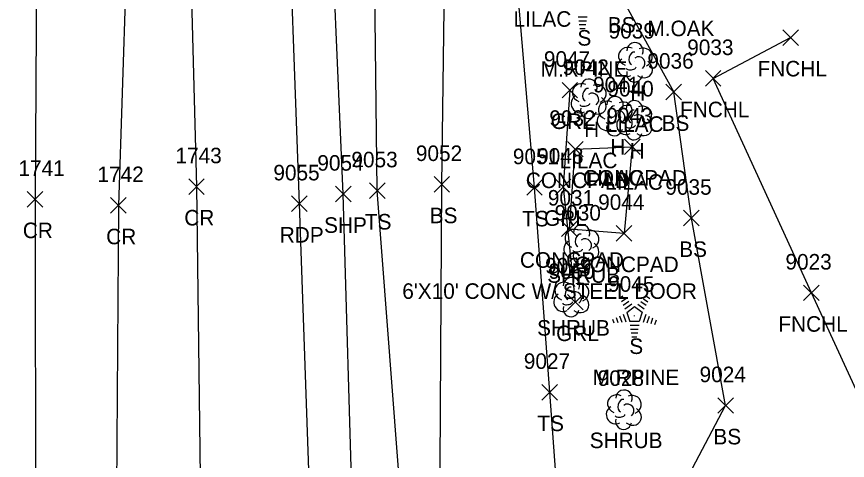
# Model space of a CAD drawing. Extents: x 1462089 to 1464015, y 730534 to 736144.
# Drawn here: x 1463213.7 to 1463320.5, y 735058.9 to 735115.9 of the extents above; entities that cross this region are included whole.
import ezdxf

# ---------------------------------------------------------------- set-up
doc = ezdxf.new("R2010")
doc.units = 0
for name, color, linetype in [('L_A', 7, 'Continuous'), ('L_C', 7, 'Continuous'), ('L_I', 7, 'Continuous'), ('L_TIC', 7, 'Continuous'), ('LELB', 7, 'Continuous'), ('LFNC', 7, 'Continuous'), ('LS', 7, 'Continuous'), ('LSH', 7, 'Continuous'), ('LTC', 7, 'Continuous'), ('LTD', 7, 'Continuous'), ('P_A', 7, 'Continuous'), ('P_I', 7, 'Continuous'), ('P_TIC', 7, 'Continuous'), ('PET', 7, 'Continuous'), ('PRC', 7, 'Continuous'), ('PSP', 7, 'Continuous'), ('R_A', 7, 'Continuous'), ('R_I', 7, 'Continuous'), ('R_TIC', 7, 'Continuous'), ('RGR', 7, 'Continuous')]:
    doc.layers.add(name, color=color, linetype=linetype)

msp = doc.modelspace()

# ---------------------------------------------------------------- linework, layer by layer
at = {"layer": 'L_TIC'}
for points in [[(1463312.17, 735112.24), (1463314.17, 735114.24)], [(1463314.17, 735112.24), (1463312.17, 735114.24)], [(1463302.21, 735106.99), (1463304.21, 735108.99)], [(1463304.21, 735106.99), (1463302.21, 735108.99)], [(1463297.15, 735105.24), (1463299.15, 735107.24)], [(1463299.15, 735105.24), (1463297.15, 735107.24)], [(1463291.82, 735098.19), (1463293.82, 735100.19)], [(1463293.82, 735098.19), (1463291.82, 735100.19)], [(1463284.48, 735097.88), (1463286.48, 735099.88)], [(1463286.48, 735097.88), (1463284.48, 735099.88)], [(1463267.33, 735093.36), (1463269.33, 735095.36)], [(1463269.33, 735093.36), (1463267.33, 735095.36)], [(1463279.24, 735092.95), (1463281.24, 735094.95)], [(1463281.24, 735092.95), (1463279.24, 735094.95)], [(1463259.03, 735092.55), (1463261.03, 735094.55)], [(1463261.03, 735092.55), (1463259.03, 735094.55)], [(1463299.41, 735089.02), (1463301.41, 735091.02)], [(1463301.41, 735089.02), (1463299.41, 735091.02)], [(1463283.73, 735087.63), (1463285.73, 735089.63)], [(1463285.73, 735087.63), (1463283.73, 735089.63)], [(1463283.73, 735087.63), (1463285.73, 735089.63)], [(1463285.73, 735087.63), (1463283.73, 735089.63)], [(1463290.76, 735087.07), (1463292.76, 735089.07)], [(1463292.76, 735087.07), (1463290.76, 735089.07)], [(1463290.76, 735087.07), (1463292.76, 735089.07)], [(1463292.76, 735087.07), (1463290.76, 735089.07)], [(1463314.85, 735079.4), (1463316.85, 735081.4)], [(1463316.85, 735079.4), (1463314.85, 735081.4)], [(1463281.2, 735066.62), (1463283.2, 735068.62)], [(1463283.2, 735066.62), (1463281.2, 735068.62)], [(1463303.81, 735064.91), (1463305.81, 735066.91)], [(1463305.81, 735064.91), (1463303.81, 735066.91)]]:
    msp.add_lwpolyline(points, dxfattribs=at)
at = {"layer": 'LELB'}
for points in [[(1463371.85, 735002), (1463364.09, 734996.08), (1463343.48, 734999.3), (1463307.3, 734996.8), (1463279.82, 735000.59), (1463268.69, 735006.74), (1463262.79, 735015.32), (1463262.16, 735022.4), (1463263.25, 735051.01), (1463260.03, 735093.55), (1463259.51, 735137.92), (1463259.23, 735169.59), (1463258.59, 735220.95), (1463257.15, 735252.7), (1463257.92, 735283.05), (1463254.46, 735323.86), (1463254.58, 735356.52), (1463254.88, 735405.06), (1463258.27, 735455.49), (1463269.4, 735506.21)], [(1463373.96, 735016.62), (1463366.71, 735008.18), (1463344.22, 735006.01), (1463305.54, 735005.28), (1463291, 735003.77), (1463271.88, 735009.52), (1463268.36, 735020.58), (1463268.05, 735051.01), (1463268.33, 735094.36), (1463268.89, 735136.34), (1463266.5, 735167.09), (1463269.8, 735218.26), (1463262.87, 735252.88), (1463272.97, 735283.56), (1463272.77, 735320.3), (1463274.69, 735357.28), (1463267.13, 735402.93), (1463272.15, 735446.53), (1463267.79, 735454.17), (1463268.05, 735456.58), (1463268.56, 735463.07), (1463267.38, 735485.54), (1463275.1, 735504.27)], [(1463291, 735003.77), (1463283.69, 735047.68), (1463282.2, 735067.62), (1463280.24, 735093.95), (1463276.56, 735137.36), (1463277.6, 735165.76), (1463292.4, 735188.02), (1463291.22, 735212.4), (1463294.67, 735266.26), (1463301.55, 735286.5), (1463304.84, 735327.55)], [(1463305.54, 735005.28), (1463294.16, 735045.7), (1463304.81, 735065.91), (1463300.41, 735090.02), (1463298.15, 735106.24), (1463291.23, 735118.87), (1463284.79, 735144.23), (1463285.45, 735166.93), (1463305.02, 735176.52), (1463314.15, 735197.89)]]:
    msp.add_lwpolyline(points, dxfattribs=at)
at = {"layer": 'LFNC'}
msp.add_lwpolyline([(1463373.96, 735016.62), (1463344.8, 735017.08), (1463329.62, 735050.54), (1463315.85, 735080.4), (1463303.21, 735107.99), (1463313.17, 735113.24)], dxfattribs=at)
at = {"layer": 'LS'}
for points in [[(1463284.73, 735088.63), (1463285.48, 735098.88), (1463292.82, 735099.19), (1463291.76, 735088.07)], [(1463284.73, 735088.63), (1463291.76, 735088.07)]]:
    msp.add_lwpolyline(points, dxfattribs=at)
at = {"layer": 'LSH'}
for p, q in [((1463286.25, 735086.7), (1463286.25, 735086.7)), ((1463286.25, 735086.7), (1463286.25, 735086.7)), ((1463284.95, 735079.9), (1463284.95, 735079.9)), ((1463284.95, 735079.9), (1463284.95, 735079.9)), ((1463291.71, 735065.43), (1463291.71, 735065.43)), ((1463291.71, 735065.43), (1463291.71, 735065.43))]:
    msp.add_line(p, q, dxfattribs=at)
for centre in [(1463286.3, 735088.13), (1463285, 735081.33), (1463291.76, 735066.86)]:
    msp.add_arc(centre, 1.05, 335.5272, 180.9563, dxfattribs=at)
for centre, major_axis, ratio, start_param, end_param in [((1463285.46, 735087.37), (1.21, -0.51), 0.895232, 1.570796, 4.712389), ((1463287.29, 735087.28), (-1.14, -0.48), 0.949671, 1.570796, 4.712389), ((1463286.04, 735087.16), (-0.208, -0.792), 0.645439, 3.141593, 6.283185), ((1463286.75, 735086.53), (-0.5, 0.667), 0.989748, 3.141593, 6.283185), ((1463285.17, 735085.99), (0.58, -1.04), 0.959034, 3.141593, 6.283185), ((1463287.25, 735085.87), (-1.09, 0.79), 0.841452, 1.570796, 4.712389), ((1463286.25, 735085.2), (0.26, 1.06), 0.942809, 1.570796, 4.712389), ((1463285.79, 735085.95), (-0.625, -0.083), 0.423636, 0, 3.141593), ((1463284.16, 735080.57), (1.21, -0.51), 0.895232, 1.570796, 4.712389), ((1463284.75, 735080.36), (-0.208, -0.792), 0.645439, 3.141593, 6.283185), ((1463286, 735080.48), (-1.14, -0.48), 0.949671, 1.570796, 4.712389), ((1463283.87, 735079.19), (0.58, -1.04), 0.959034, 3.141593, 6.283185), ((1463285.45, 735079.73), (-0.5, 0.667), 0.989748, 3.141593, 6.283185), ((1463285.95, 735079.07), (-1.09, 0.79), 0.841452, 1.570796, 4.712389), ((1463284.5, 735079.15), (-0.625, -0.083), 0.423636, 0, 3.141593), ((1463284.95, 735078.4), (0.26, 1.06), 0.942809, 1.570796, 4.712389), ((1463290.92, 735066.09), (1.21, -0.51), 0.895232, 1.570796, 4.712389), ((1463292.75, 735066.01), (-1.14, -0.48), 0.949671, 1.570796, 4.712389), ((1463291.5, 735065.89), (-0.208, -0.792), 0.645439, 3.141593, 6.283185), ((1463292.21, 735065.26), (-0.5, 0.667), 0.989748, 3.141593, 6.283185), ((1463290.63, 735064.72), (0.58, -1.04), 0.959034, 3.141593, 6.283185), ((1463292.71, 735064.59), (-1.09, 0.79), 0.841452, 1.570796, 4.712389), ((1463291.71, 735063.93), (0.26, 1.06), 0.942809, 1.570796, 4.712389), ((1463291.25, 735064.68), (-0.625, -0.083), 0.423636, 0, 3.141593)]:
    msp.add_ellipse(centre, major_axis=major_axis, ratio=ratio, start_param=start_param, end_param=end_param, dxfattribs=at)
at = {"layer": 'LTC'}
for p, q in [((1463287, 735115.87), (1463285.86, 735115.87)), ((1463286.92, 735115.37), (1463285.93, 735115.37)), ((1463286.84, 735114.87), (1463286, 735114.87)), ((1463286.75, 735114.37), (1463286.08, 735114.37)), ((1463291.24, 735079.75), (1463291.6, 735080)), ((1463294.64, 735079.99), (1463295.06, 735079.68)), ((1463291.45, 735079.28), (1463291.98, 735079.67)), ((1463291.66, 735078.82), (1463292.37, 735079.33)), ((1463291.87, 735078.35), (1463292.75, 735078.99)), ((1463293.53, 735078.94), (1463294.34, 735078.35)), ((1463293.9, 735079.29), (1463294.58, 735078.8)), ((1463294.27, 735079.64), (1463294.82, 735079.24)), ((1463291.64, 735077.68), (1463291.97, 735076.66)), ((1463292.1, 735077.89), (1463293.11, 735078.63)), ((1463292.1, 735077.89), (1463292.48, 735076.7)), ((1463293.11, 735078.63), (1463294.1, 735077.9)), ((1463294.1, 735077.9), (1463293.71, 735076.7)), ((1463290.28, 735077.03), (1463290.43, 735076.56)), ((1463290.73, 735077.24), (1463290.94, 735076.59)), ((1463291.19, 735077.46), (1463291.46, 735076.62)), ((1463293.71, 735076.7), (1463292.48, 735076.7)), ((1463294.54, 735077.63), (1463294.2, 735076.59)), ((1463294.99, 735077.38), (1463294.7, 735076.5)), ((1463295.43, 735077.13), (1463295.19, 735076.4)), ((1463295.88, 735076.88), (1463295.69, 735076.31)), ((1463293.68, 735076.2), (1463292.53, 735076.2)), ((1463293.59, 735075.7), (1463292.6, 735075.7)), ((1463293.51, 735075.2), (1463292.68, 735075.2)), ((1463293.42, 735074.7), (1463292.75, 735074.7))]:
    msp.add_line(p, q, dxfattribs=at)
at = {"layer": 'LTD'}
for p, q in [((1463293.13, 735110.11), (1463293.13, 735110.11)), ((1463293.13, 735110.11), (1463293.13, 735110.11)), ((1463287.19, 735105.43), (1463287.19, 735105.43)), ((1463287.19, 735105.43), (1463287.19, 735105.43)), ((1463290.54, 735103.19), (1463290.54, 735103.19)), ((1463290.54, 735103.19), (1463290.54, 735103.19)), ((1463293.05, 735102.66), (1463293.05, 735102.66)), ((1463293.05, 735102.66), (1463293.05, 735102.66))]:
    msp.add_line(p, q, dxfattribs=at)
for centre in [(1463293.17, 735111.55), (1463287.24, 735106.86), (1463290.59, 735104.62), (1463293.09, 735104.09)]:
    msp.add_arc(centre, 1.05, 335.5272, 180.9563, dxfattribs=at)
for centre, major_axis, ratio, start_param, end_param in [((1463292.34, 735110.78), (1.21, -0.51), 0.895232, 1.570796, 4.712389), ((1463294.17, 735110.69), (-1.14, -0.48), 0.949671, 1.570796, 4.712389), ((1463292.92, 735110.57), (-0.208, -0.792), 0.645439, 3.141593, 6.283185), ((1463293.63, 735109.94), (-0.5, 0.667), 0.989748, 3.141593, 6.283185), ((1463292.04, 735109.4), (0.58, -1.04), 0.959034, 3.141593, 6.283185), ((1463294.13, 735109.28), (-1.09, 0.79), 0.841452, 1.570796, 4.712389), ((1463293.13, 735108.61), (0.26, 1.06), 0.942809, 1.570796, 4.712389), ((1463292.67, 735109.36), (-0.625, -0.083), 0.423636, 0, 3.141593), ((1463286.4, 735106.1), (1.21, -0.51), 0.895232, 1.570796, 4.712389), ((1463286.98, 735105.89), (-0.208, -0.792), 0.645439, 3.141593, 6.283185), ((1463288.23, 735106.01), (-1.14, -0.48), 0.949671, 1.570796, 4.712389), ((1463286.11, 735104.72), (0.58, -1.04), 0.959034, 3.141593, 6.283185), ((1463287.69, 735105.26), (-0.5, 0.667), 0.989748, 3.141593, 6.283185), ((1463288.19, 735104.6), (-1.09, 0.79), 0.841452, 1.570796, 4.712389), ((1463286.73, 735104.68), (-0.625, -0.083), 0.423636, 0, 3.141593), ((1463289.75, 735103.86), (1.21, -0.51), 0.895232, 1.570796, 4.712389), ((1463290.34, 735103.65), (-0.208, -0.792), 0.645439, 3.141593, 6.283185), ((1463292.26, 735103.32), (1.21, -0.51), 0.895232, 1.570796, 4.712389), ((1463291.59, 735103.77), (-1.14, -0.48), 0.949671, 1.570796, 4.712389), ((1463294.09, 735103.24), (-1.14, -0.48), 0.949671, 1.570796, 4.712389), ((1463287.19, 735103.93), (0.26, 1.06), 0.942809, 1.570796, 4.712389), ((1463289.46, 735102.48), (0.58, -1.04), 0.959034, 3.141593, 6.283185), ((1463291.04, 735103.02), (-0.5, 0.667), 0.989748, 3.141593, 6.283185), ((1463292.84, 735103.12), (-0.208, -0.792), 0.645439, 3.141593, 6.283185), ((1463293.55, 735102.49), (-0.5, 0.667), 0.989748, 3.141593, 6.283185), ((1463290.09, 735102.44), (-0.625, -0.083), 0.423636, 0, 3.141593), ((1463291.96, 735101.95), (0.58, -1.04), 0.959034, 3.141593, 6.283185), ((1463291.54, 735102.36), (-1.09, 0.79), 0.841452, 1.570796, 4.712389), ((1463294.05, 735101.83), (-1.09, 0.79), 0.841452, 1.570796, 4.712389), ((1463290.54, 735101.69), (0.26, 1.06), 0.942809, 1.570796, 4.712389), ((1463293.05, 735101.16), (0.26, 1.06), 0.942809, 1.570796, 4.712389), ((1463292.59, 735101.91), (-0.625, -0.083), 0.423636, 0, 3.141593)]:
    msp.add_ellipse(centre, major_axis=major_axis, ratio=ratio, start_param=start_param, end_param=end_param, dxfattribs=at)
at = {"layer": 'P_TIC'}
for points in [[(1463235.78, 735093.07), (1463237.78, 735095.07)], [(1463237.78, 735093.07), (1463235.78, 735095.07)], [(1463254.66, 735092.12), (1463256.66, 735094.12)], [(1463256.66, 735092.12), (1463254.66, 735094.12)], [(1463215.02, 735091.44), (1463217.02, 735093.44)], [(1463217.02, 735091.44), (1463215.02, 735093.44)], [(1463225.74, 735090.65), (1463227.74, 735092.65)], [(1463227.74, 735090.65), (1463225.74, 735092.65)], [(1463249.01, 735090.87), (1463251.01, 735092.87)], [(1463251.01, 735090.87), (1463249.01, 735092.87)]]:
    msp.add_lwpolyline(points, dxfattribs=at)
at = {"layer": 'PET'}
msp.add_lwpolyline([(1463255.03, 734720.12), (1463254.12, 734771.84), (1463253.55, 734825), (1463253.11, 734864.1), (1463252.5, 734904.18), (1463252.01, 734932.91), (1463252.21, 734977.68), (1463251.97, 735017.67), (1463251.42, 735051.49), (1463250.01, 735091.87), (1463248.35, 735137.79), (1463247.11, 735168.04), (1463244.5, 735220.45), (1463242.66, 735256.85), (1463241.98, 735280.77), (1463241.22, 735323.55), (1463241.58, 735355.89), (1463243.82, 735405.25), (1463248.55, 735456.35), (1463255.13, 735496.28)], dxfattribs=at)
at = {"layer": 'PRC'}
for points in [[(1463243.54, 735500.8), (1463236.92, 735460.01), (1463232.14, 735413.46), (1463229.79, 735375.51), (1463228.93, 735324.03), (1463227.87, 735282.52), (1463228.15, 735235.1), (1463227.86, 735197.88), (1463228.62, 735149.63), (1463226.74, 735091.65), (1463226.45, 735049), (1463226.35, 735007.34), (1463227.1, 734963.18), (1463227.71, 734927.41), (1463228.78, 734878.14), (1463228.9, 734842.02), (1463228.58, 734798.08), (1463230.75, 734747.1)], [(1463216.67, 735366.03), (1463218.87, 735371.39), (1463218.13, 735319.85), (1463217.07, 735284.13), (1463217.19, 735234.76), (1463216.07, 735198.92), (1463216.37, 735151.27), (1463216.02, 735092.44), (1463216.08, 735049.13), (1463213.65, 735007.29), (1463214.1, 734963.88), (1463214.18, 734928.27), (1463216.39, 734879.15), (1463217.01, 734842.19), (1463217.11, 734797.78), (1463218.92, 734749.04)], [(1463228.93, 735324.03), (1463229.27, 735282.53), (1463230.92, 735235.37), (1463232.41, 735197.7), (1463235.31, 735148.71), (1463236.78, 735094.07), (1463237.32, 735049.95), (1463238.75, 735006.91), (1463239.78, 734964.48), (1463240.55, 734927.63), (1463240.74, 734877.14), (1463241.22, 734842.28), (1463241.52, 734797.52), (1463242.3, 734746.35)]]:
    msp.add_lwpolyline(points, dxfattribs=at)
at = {"layer": 'PSP'}
msp.add_lwpolyline([(1463260.61, 734721.09), (1463259.81, 734771.37), (1463258.83, 734825.03), (1463258.44, 734864.28), (1463257.81, 734904.18), (1463257.86, 734929.75), (1463257.64, 734971.1), (1463257.12, 734983.28), (1463257.63, 735017.78), (1463256.87, 735050.62), (1463255.66, 735093.12), (1463253.72, 735137.76), (1463252.7, 735169.76), (1463249.36, 735221.18), (1463247.14, 735255.65), (1463245.42, 735280.67), (1463244.78, 735323.8), (1463245.26, 735355.71), (1463246.85, 735405.2), (1463251.22, 735455.98), (1463269.22, 735540.32), (1463284.02, 735584.42), (1463301.55, 735626.26)], dxfattribs=at)
at = {"layer": 'R_TIC'}
for points in [[(1463283.79, 735105.48), (1463285.79, 735107.48)], [(1463285.79, 735105.48), (1463283.79, 735107.48)], [(1463282.93, 735093.02), (1463284.93, 735095.02)], [(1463284.93, 735093.02), (1463282.93, 735095.02)], [(1463284.48, 735078.2), (1463286.48, 735080.2)], [(1463286.48, 735078.2), (1463284.48, 735080.2)]]:
    msp.add_lwpolyline(points, dxfattribs=at)
at = {"layer": 'RGR'}
msp.add_lwpolyline([(1463284.79, 735106.48), (1463283.93, 735094.02), (1463285.48, 735079.2)], dxfattribs=at)

# ---------------------------------------------------------------- texts
at = {"layer": 'L_A'}
for s, p in [('BS', (1463289.67, 735113.87)), ('S', (1463285.76, 735112.2)), ('FNCHL', (1463308.92, 735108.24)), ('H', (1463292.56, 735105.11)), ('FNCHL', (1463298.96, 735102.99)), ('H', (1463286.63, 735100.43)), ('BS', (1463296.59, 735101.24)), ('H', (1463289.98, 735098.19)), ('H', (1463292.48, 735097.66)), ('CONCPAD', (1463279.13, 735093.88)), ('CONCPAD', (1463286.47, 735094.19)), ('TS', (1463258.44, 735088.55)), ('BS', (1463266.77, 735089.36)), ('TS', (1463278.65, 735088.95)), ('BS', (1463298.85, 735085.02)), ('CONCPAD', (1463278.37, 735083.63)), ('CONCPAD', (1463278.37, 735083.63)), ('CONCPAD', (1463285.41, 735083.07)), ('CONCPAD', (1463285.41, 735083.07)), ('SHRUB', (1463281.88, 735081.7)), ('SHRUB', (1463280.58, 735074.9)), ('FNCHL', (1463311.6, 735075.4)), ('S', (1463292.43, 735072.54)), ('TS', (1463280.61, 735062.62)), ('BS', (1463303.25, 735060.91)), ('SHRUB', (1463287.34, 735060.43))]:
    msp.add_text(s, height=2, dxfattribs=at).set_placement(p)
at = {"layer": 'L_C'}
for s, p in [('LILAC', (1463277.54, 735114.63)), ('M.OAK', (1463294.76, 735113.42)), ('M.RPINE', (1463281.04, 735108.2)), ('LILAC', (1463289.4, 735101.11)), ('LILAC', (1463283.47, 735096.43)), ('LILAC', (1463286.82, 735094.19)), ('LILAC', (1463289.32, 735093.66)), ("6'X10' CONC W/ STEEL DOOR", (1463263.24, 735079.63)), ("6'X10' CONC W/ STEEL DOOR", (1463263.24, 735079.63)), ('M.RPINE', (1463287.71, 735068.54))]:
    msp.add_text(s, height=2, dxfattribs=at).set_placement(p)
at = {"layer": 'L_I'}
for s, p in [('9039', (1463289.78, 735113.11)), ('9033', (1463299.88, 735110.99)), ('9036', (1463294.76, 735109.24)), ('9042', (1463283.85, 735108.43)), ('9041', (1463287.77, 735106.19)), ('9040', (1463289.62, 735105.66)), ('9032', (1463282.15, 735101.88)), ('9043', (1463289.48, 735102.19)), ('9052', (1463264.99, 735097.36)), ('9053', (1463256.7, 735096.55)), ('9051', (1463277.46, 735096.95)), ('9035', (1463297.07, 735093.02)), ('9031', (1463281.96, 735091.63)), ('9031', (1463281.96, 735091.63)), ('9044', (1463288.43, 735091.07)), ('9044', (1463288.43, 735091.07)), ('9030', (1463282.83, 735089.7)), ('9023', (1463312.51, 735083.4)), ('9029', (1463281.61, 735082.9)), ('9045', (1463289.71, 735080.54)), ('9027', (1463278.87, 735070.62)), ('9028', (1463288.37, 735068.43)), ('9024', (1463301.47, 735068.91))]:
    msp.add_text(s, height=2, dxfattribs=at).set_placement(p)
at = {"layer": 'LTC'}
msp.add_text('.', height=1.04, rotation=270, dxfattribs=at).set_placement((1463292.99, 735077.64))
at = {"layer": 'P_A'}
for s, p in [('CR', (1463235.21, 735089.07)), ('CR', (1463214.45, 735087.44)), ('SHP', (1463253.19, 735088.12)), ('CR', (1463225.17, 735086.65)), ('RDP', (1463247.49, 735086.87))]:
    msp.add_text(s, height=2, dxfattribs=at).set_placement(p)
at = {"layer": 'P_I'}
for s, p in [('1743', (1463234.08, 735097.07)), ('9054', (1463252.32, 735096.12)), ('1741', (1463213.89, 735095.44)), ('9055', (1463246.67, 735094.87)), ('1742', (1463224.05, 735094.65))]:
    msp.add_text(s, height=2, dxfattribs=at).set_placement(p)
at = {"layer": 'R_A'}
for p in [(1463282.33, 735101.48), (1463281.47, 735089.02), (1463283.02, 735074.2)]:
    msp.add_text('GRL', height=2, dxfattribs=at).set_placement(p)
at = {"layer": 'R_I'}
for s, p in [('9047', (1463281.45, 735109.48)), ('9048', (1463280.59, 735097.02)), ('9050', (1463282.05, 735082.2))]:
    msp.add_text(s, height=2, dxfattribs=at).set_placement(p)

doc.saveas('drawing.dxf')
